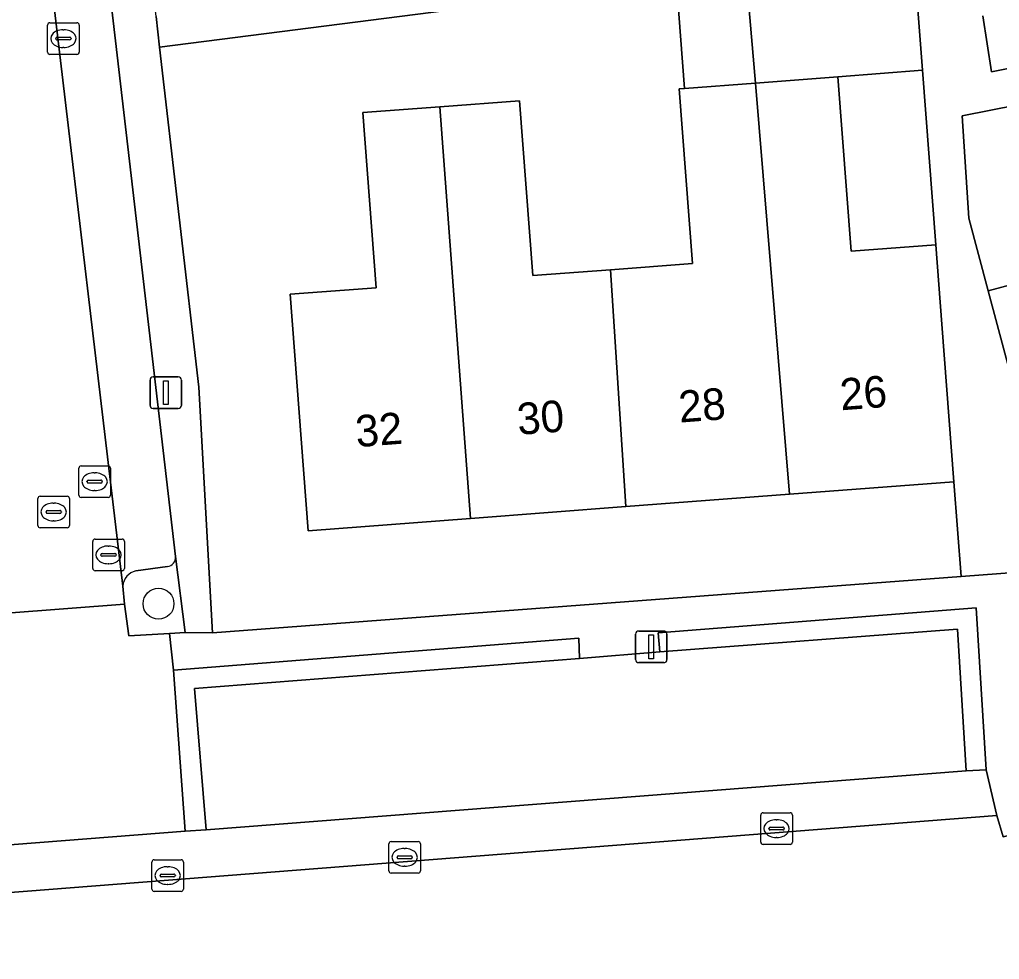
# Model space of a CAD drawing. Extents: x 162250 to 162661, y 380743 to 381606.
# Drawn here: x 162465.47 to 162496.44, y 380953.52 to 380983.23 of the extents above; entities that cross this region are included whole.
import ezdxf

# ---------------------------------------------------------------- set-up
doc = ezdxf.new("R2010")
doc.units = 0
for name, color, linetype in [('IMGEO_Boom', 7, 'Continuous'), ('IMGEO_Erf', 7, 'Continuous'), ('IMGEO_Groenvoorziening', 7, 'Continuous'), ('IMGEO_Haag', 7, 'Continuous'), ('IMGEO_Kolk', 7, 'Continuous'), ('IMGEO_Lichtmast', 7, 'Continuous'), ('IMGEO_Pand', 7, 'Continuous'), ('IMGEO_Pand_nummerreeks', 7, 'Continuous'), ('IMGEO_Parkeervlak_open', 7, 'Continuous'), ('IMGEO_Rijbaan_lokaal_open', 7, 'Continuous'), ('IMGEO_Rioolput', 7, 'Continuous'), ('IMGEO_Voetpad_open', 7, 'Continuous')]:
    doc.layers.add(name, color=color, linetype=linetype)

msp = doc.modelspace()

# ---------------------------------------------------------------- linework, layer by layer
at = {"layer": 'IMGEO_Boom'}
msp.add_circle((162469.861, 380964.762), 0.489, dxfattribs=at)
at = {"layer": 'IMGEO_Erf'}
for points in [[(162486.322, 380981.042), (162486.481, 380981.054), (162486.238, 380984.254), (162488.449, 380984.535), (162493.737, 380985.206), (162493.721, 380985.411), (162469.897, 380982.357), (162471.135, 380971.612), (162471.572, 380963.846), (162495.227, 380965.622), (162494.999, 380968.619), (162489.799, 380968.224), (162484.636, 380967.831), (162479.725, 380967.457), (162474.59, 380967.067), (162474.021, 380974.546), (162476.744, 380974.753), (162476.323, 380980.291), (162478.756, 380980.476), (162481.27, 380980.667), (162481.691, 380975.136), (162484.148, 380975.323), (162486.742, 380975.52)], [(162494.009, 380981.627), (162491.33, 380981.423), (162491.75, 380975.909), (162494.429, 380976.113)]]:
    msp.add_lwpolyline(points, close=True, dxfattribs=at)
for points in [[(162514.514, 380984.008), (162495.265, 380980.189), (162495.468, 380976.95), (162496.082, 380974.653), (162498.633, 380975.335)], [(162495.915, 380983.354), (162496.184, 380981.582), (162509.432, 380984.21)]]:
    msp.add_lwpolyline(points, dxfattribs=at)
at = {"layer": 'IMGEO_Groenvoorziening'}
for points in [[(162468.735, 380965.321), (162468.787, 380964.749), (162468.925, 380963.744), (162470.212, 380963.82), (162470.699, 380963.849), (162470.398, 380966.255)], [(162470.141, 380965.934), (162469.147, 380965.797)]]:
    msp.add_lwpolyline(points, dxfattribs=at)
for points in [[(162496.019, 380959.507), (162495.7, 380964.636), (162485.657, 380963.842), (162485.706, 380963.237), (162495.115, 380963.958), (162495.387, 380959.475)], [(162471.001, 380962.077), (162483.168, 380963.025), (162483.148, 380963.671), (162470.338, 380962.659), (162470.708, 380957.569), (162471.37, 380957.614)]]:
    msp.add_lwpolyline(points, close=True, dxfattribs=at)
for centre, radius, start, end in [((162470.106, 380966.226), 0.294, 276.9, 5.7368), ((162469.25, 380965.291), 0.516, 101.555, 176.6896)]:
    msp.add_arc(centre, radius, start, end, dxfattribs=at)
at = {"layer": 'IMGEO_Haag'}
for points in [[(162496.019, 380959.507), (162495.7, 380964.636), (162485.657, 380963.842), (162485.706, 380963.237), (162495.115, 380963.958), (162495.387, 380959.475)], [(162471.001, 380962.077), (162483.168, 380963.025), (162483.148, 380963.671), (162470.338, 380962.659), (162470.708, 380957.569), (162471.37, 380957.614)]]:
    msp.add_lwpolyline(points, close=True, dxfattribs=at)
at = {"layer": 'IMGEO_Kolk'}
for p, q in [((162466.354, 380982.204), (162466.354, 380983.056)), ((162466.429, 380983.13), (162467.281, 380983.13)), ((162467.355, 380983.056), (162467.355, 380982.204)), ((162466.842, 380982.91), (162466.867, 380982.91)), ((162466.613, 380982.624), (162466.613, 380982.636)), ((162467.051, 380982.587), (162466.653, 380982.587)), ((162466.656, 380982.673), (162467.054, 380982.673)), ((162467.097, 380982.636), (162467.097, 380982.624)), ((162467.281, 380982.13), (162466.429, 380982.13)), ((162466.865, 380982.35), (162466.84, 380982.35)), ((162467.417, 380969.121), (162468.269, 380969.121)), ((162467.342, 380968.195), (162467.342, 380969.047)), ((162467.83, 380968.901), (162467.855, 380968.901)), ((162468.343, 380969.047), (162468.343, 380968.195)), ((162467.601, 380968.615), (162467.601, 380968.627)), ((162468.039, 380968.578), (162467.641, 380968.578)), ((162467.644, 380968.664), (162468.042, 380968.664)), ((162468.085, 380968.627), (162468.085, 380968.615)), ((162467.853, 380968.341), (162467.828, 380968.341)), ((162468.269, 380968.121), (162467.417, 380968.121)), ((162488.894, 380957.225), (162488.894, 380958.077)), ((162488.969, 380958.151), (162489.821, 380958.151)), ((162489.895, 380958.077), (162489.895, 380957.225)), ((162489.153, 380957.645), (162489.153, 380957.657)), ((162489.196, 380957.694), (162489.594, 380957.694)), ((162489.382, 380957.931), (162489.407, 380957.931)), ((162489.637, 380957.657), (162489.637, 380957.645)), ((162489.591, 380957.608), (162489.193, 380957.608)), ((162489.405, 380957.371), (162489.38, 380957.371)), ((162477.14, 380956.317), (162477.14, 380957.169)), ((162477.215, 380957.243), (162478.067, 380957.243)), ((162477.628, 380957.023), (162477.653, 380957.023)), ((162478.141, 380957.169), (162478.141, 380956.317)), ((162489.821, 380957.151), (162488.969, 380957.151)), ((162477.399, 380956.737), (162477.399, 380956.749)), ((162477.442, 380956.786), (162477.84, 380956.786)), ((162477.883, 380956.749), (162477.883, 380956.737)), ((162469.65, 380955.741), (162469.65, 380956.593)), ((162469.725, 380956.667), (162470.577, 380956.667)), ((162470.138, 380956.447), (162470.163, 380956.447)), ((162470.651, 380956.593), (162470.651, 380955.741)), ((162477.837, 380956.7), (162477.439, 380956.7)), ((162477.651, 380956.463), (162477.626, 380956.463)), ((162469.909, 380956.161), (162469.909, 380956.173)), ((162470.347, 380956.124), (162469.949, 380956.124)), ((162469.952, 380956.21), (162470.35, 380956.21)), ((162470.393, 380956.173), (162470.393, 380956.161)), ((162478.067, 380956.243), (162477.215, 380956.243)), ((162470.161, 380955.887), (162470.136, 380955.887)), ((162470.577, 380955.667), (162469.725, 380955.667))]:
    msp.add_line(p, q, dxfattribs=at)
for points in [[(162466.354, 380982.204), (162466.354, 380983.056)], [(162466.429, 380983.13), (162467.281, 380983.13)], [(162467.355, 380983.056), (162467.355, 380982.204)], [(162467.281, 380982.13), (162466.429, 380982.13)], [(162467.417, 380969.121), (162468.269, 380969.121)], [(162467.342, 380968.195), (162467.342, 380969.047)], [(162468.343, 380969.047), (162468.343, 380968.195)], [(162468.269, 380968.121), (162467.417, 380968.121)], [(162488.894, 380957.225), (162488.894, 380958.077)], [(162488.969, 380958.151), (162489.821, 380958.151)], [(162489.895, 380958.077), (162489.895, 380957.225)], [(162477.14, 380956.317), (162477.14, 380957.169)], [(162477.215, 380957.243), (162478.067, 380957.243)], [(162478.141, 380957.169), (162478.141, 380956.317)], [(162489.821, 380957.151), (162488.969, 380957.151)], [(162469.65, 380955.741), (162469.65, 380956.593)], [(162469.725, 380956.667), (162470.577, 380956.667)], [(162470.651, 380956.593), (162470.651, 380955.741)], [(162478.067, 380956.243), (162477.215, 380956.243)], [(162470.577, 380955.667), (162469.725, 380955.667)]]:
    msp.add_lwpolyline(points, dxfattribs=at)
for centre, radius, start, end in [((162466.431, 380983.054), 0.0765, 91.552, 178.448), ((162466.431, 380983.054), 0.0765, 91.552, 178.448), ((162467.279, 380983.054), 0.0765, 1.552, 88.448), ((162467.279, 380983.054), 0.0765, 1.552, 88.448), ((162466.653, 380982.633), 0.0403, 85.8775, 175.7526), ((162466.65, 380982.623), 0.0366, 178.938, 274.7102), ((162467.054, 380982.63), 0.043, 264.8664, 352.4533), ((162467.058, 380982.635), 0.0386, 1.7309, 96.639), ((162466.431, 380982.206), 0.0765, 181.552, 268.448), ((162466.431, 380982.206), 0.0765, 181.552, 268.448), ((162467.279, 380982.206), 0.0765, 271.552, 358.448), ((162467.279, 380982.206), 0.0765, 271.552, 358.448), ((162467.419, 380969.045), 0.0765, 91.552, 178.448), ((162467.419, 380969.045), 0.0765, 91.552, 178.448), ((162468.267, 380969.045), 0.0765, 1.552, 88.448), ((162468.267, 380969.045), 0.0765, 1.552, 88.448), ((162467.641, 380968.624), 0.0403, 85.8775, 175.7526), ((162467.638, 380968.614), 0.0366, 178.938, 274.7102), ((162468.042, 380968.621), 0.043, 264.8664, 352.4533), ((162468.046, 380968.626), 0.0386, 1.7309, 96.639), ((162467.419, 380968.197), 0.0765, 181.552, 268.448), ((162467.419, 380968.197), 0.0765, 181.552, 268.448), ((162468.267, 380968.197), 0.0765, 271.552, 358.448), ((162468.267, 380968.197), 0.0765, 271.552, 358.448), ((162488.971, 380958.075), 0.0765, 91.552, 178.448), ((162488.971, 380958.075), 0.0765, 91.552, 178.448), ((162489.819, 380958.075), 0.0765, 1.552, 88.448), ((162489.819, 380958.075), 0.0765, 1.552, 88.448), ((162489.193, 380957.654), 0.0403, 85.8775, 175.7526), ((162489.19, 380957.644), 0.0366, 178.938, 274.7102), ((162489.594, 380957.651), 0.043, 264.8664, 352.4533), ((162489.598, 380957.656), 0.0386, 1.7309, 96.639), ((162477.217, 380957.167), 0.0765, 91.552, 178.448), ((162477.217, 380957.167), 0.0765, 91.552, 178.448), ((162478.065, 380957.167), 0.0765, 1.552, 88.448), ((162478.065, 380957.167), 0.0765, 1.552, 88.448), ((162488.971, 380957.227), 0.0765, 181.552, 268.448), ((162488.971, 380957.227), 0.0765, 181.552, 268.448), ((162489.819, 380957.227), 0.0765, 271.552, 358.448), ((162489.819, 380957.227), 0.0765, 271.552, 358.448), ((162477.439, 380956.746), 0.0403, 85.8775, 175.7526), ((162477.436, 380956.736), 0.0366, 178.938, 274.7102), ((162477.84, 380956.743), 0.043, 264.8664, 352.4533), ((162477.844, 380956.748), 0.0386, 1.7309, 96.639), ((162469.727, 380956.591), 0.0765, 91.552, 178.448), ((162469.727, 380956.591), 0.0765, 91.552, 178.448), ((162470.575, 380956.591), 0.0765, 1.552, 88.448), ((162470.575, 380956.591), 0.0765, 1.552, 88.448), ((162469.949, 380956.17), 0.0403, 85.8775, 175.7526), ((162469.946, 380956.16), 0.0366, 178.938, 274.7102), ((162470.35, 380956.167), 0.043, 264.8664, 352.4533), ((162470.354, 380956.172), 0.0386, 1.7309, 96.639), ((162477.217, 380956.319), 0.0765, 181.552, 268.448), ((162477.217, 380956.319), 0.0765, 181.552, 268.448), ((162478.065, 380956.319), 0.0765, 271.552, 358.448), ((162478.065, 380956.319), 0.0765, 271.552, 358.448), ((162469.727, 380955.743), 0.0765, 181.552, 268.448), ((162469.727, 380955.743), 0.0765, 181.552, 268.448), ((162470.575, 380955.743), 0.0765, 271.552, 358.448), ((162470.575, 380955.743), 0.0765, 271.552, 358.448)]:
    msp.add_arc(centre, radius, start, end, dxfattribs=at)
for centre, major_axis, ratio, start_param, end_param in [((162466.841, 380982.63), (-0.387, 0.002), 0.722429, 4.712389, 7.853982), ((162466.866, 380982.63), (-0.39, 0.002), 0.717154, 1.570796, 4.712389), ((162467.829, 380968.621), (-0.387, 0.002), 0.722429, 4.712389, 7.853982), ((162467.854, 380968.621), (-0.39, 0.002), 0.717154, 1.570796, 4.712389), ((162489.381, 380957.651), (-0.387, 0.002), 0.722429, 4.712389, 7.853982), ((162489.406, 380957.651), (-0.39, 0.002), 0.717154, 1.570796, 4.712389), ((162477.627, 380956.743), (-0.387, 0.002), 0.722429, 4.712389, 7.853982), ((162477.652, 380956.743), (-0.39, 0.002), 0.717154, 1.570796, 4.712389), ((162470.137, 380956.167), (-0.387, 0.002), 0.722429, 4.712389, 7.853982), ((162470.162, 380956.167), (-0.39, 0.002), 0.717154, 1.570796, 4.712389)]:
    msp.add_ellipse(centre, major_axis=major_axis, ratio=ratio, start_param=start_param, end_param=end_param, dxfattribs=at)
at = {"layer": 'IMGEO_Lichtmast'}
for p, q in [((162469.694, 380971.933), (162470.484, 380971.933)), ((162470.484, 380971.933), (162469.694, 380971.933)), ((162469.594, 380971.033), (162469.594, 380971.833)), ((162469.594, 380971.833), (162469.594, 380971.033)), ((162470.584, 380971.833), (162470.584, 380971.033)), ((162470.584, 380971.033), (162470.584, 380971.833)), ((162470.484, 380970.933), (162469.694, 380970.933)), ((162469.694, 380970.933), (162470.484, 380970.933)), ((162485.04, 380963.899), (162485.83, 380963.899)), ((162485.83, 380963.899), (162485.04, 380963.899)), ((162484.94, 380962.999), (162484.94, 380963.799)), ((162484.94, 380963.799), (162484.94, 380962.999)), ((162485.93, 380963.799), (162485.93, 380962.999)), ((162485.93, 380962.999), (162485.93, 380963.799)), ((162485.83, 380962.899), (162485.04, 380962.899)), ((162485.04, 380962.899), (162485.83, 380962.899))]:
    msp.add_line(p, q, dxfattribs=at)
for points in [[(162470.014, 380971.808), (162470.164, 380971.808), (162470.164, 380971.058), (162470.014, 380971.058), (162470.014, 380971.808)], [(162485.36, 380963.774), (162485.51, 380963.774), (162485.51, 380963.024), (162485.36, 380963.024), (162485.36, 380963.774)]]:
    msp.add_lwpolyline(points, dxfattribs=at)
for centre, start, end in [((162469.694, 380971.833), 90, 180), ((162469.694, 380971.833), 90, 180), ((162470.484, 380971.833), 0, 90), ((162470.484, 380971.833), 360, 90), ((162469.694, 380971.033), 180, 270), ((162469.694, 380971.033), 180, 270), ((162470.484, 380971.033), 270, 0), ((162470.484, 380971.033), 270, 0), ((162485.04, 380963.799), 90, 180), ((162485.04, 380963.799), 90, 180), ((162485.83, 380963.799), 0, 90), ((162485.83, 380963.799), 360, 90), ((162485.04, 380962.999), 180, 270), ((162485.04, 380962.999), 180, 270), ((162485.83, 380962.999), 270, 0), ((162485.83, 380962.999), 270, 0)]:
    msp.add_arc(centre, 0.1, start, end, dxfattribs=at)
at = {"layer": 'IMGEO_Pand'}
for points in [[(162493.737, 380985.206), (162488.449, 380984.535), (162488.728, 380981.225), (162491.33, 380981.423), (162494.009, 380981.627)], [(162488.449, 380984.535), (162486.238, 380984.254), (162486.481, 380981.054), (162488.728, 380981.225)], [(162488.728, 380981.225), (162486.481, 380981.054), (162486.322, 380981.042), (162486.742, 380975.52), (162484.148, 380975.323), (162484.636, 380967.831), (162489.799, 380968.224)], [(162488.728, 380981.225), (162489.799, 380968.224), (162494.999, 380968.619), (162494.62, 380973.605), (162494.429, 380976.113), (162491.75, 380975.909), (162491.33, 380981.423)], [(162478.756, 380980.476), (162479.725, 380967.457), (162484.636, 380967.831), (162484.148, 380975.323), (162481.691, 380975.136), (162481.27, 380980.667)], [(162478.756, 380980.476), (162476.323, 380980.291), (162476.744, 380974.753), (162474.021, 380974.546), (162474.59, 380967.067), (162479.725, 380967.457)], [(162500.261, 380978.292), (162500, 380978.222), (162498.004, 380977.689), (162498.633, 380975.335), (162496.082, 380974.653), (162498.432, 380965.863), (162498.83, 380964.374), (162500, 380964.687), (162503.731, 380965.684)]]:
    msp.add_lwpolyline(points, close=True, dxfattribs=at)
at = {"layer": 'IMGEO_Parkeervlak_open'}
for points in [[(162466.443, 380984.612), (162468.735, 380965.321)], [(162470.398, 380966.255), (162468.323, 380984.109)], [(162469.147, 380965.797), (162470.141, 380965.934)]]:
    msp.add_lwpolyline(points, dxfattribs=at)
msp.add_lwpolyline([(162485.706, 380963.237), (162483.168, 380963.025), (162471.001, 380962.077), (162471.37, 380957.614), (162495.387, 380959.475), (162495.115, 380963.958)], close=True, dxfattribs=at)
for centre, radius, start, end in [((162470.106, 380966.226), 0.294, 276.9, 5.7368), ((162469.25, 380965.291), 0.516, 101.555, 176.6896)]:
    msp.add_arc(centre, radius, start, end, dxfattribs=at)
at = {"layer": 'IMGEO_Rijbaan_lokaal_open'}
for points in [[(162460.5, 381035.516), (162460.418, 381036.093), (162456.733, 381035.695), (162458.261, 381022.719), (162458.412, 381021.524), (162461.237, 380997.285), (162461.392, 380996.087), (162464.213, 380971.852), (162464.376, 380970.663), (162465.07, 380964.466), (162468.787, 380964.749), (162468.735, 380965.321), (162466.443, 380984.612), (162466.298, 380985.818), (162463.47, 381010.085), (162463.312, 381011.262)], [(162470.338, 380962.659), (162470.212, 380963.82), (162468.925, 380963.744), (162468.787, 380964.749), (162465.07, 380964.466), (162465.132, 380963.42), (162463.931, 380963.326), (162463.987, 380962.195), (162464.477, 380957.086), (162470.708, 380957.569)], [(162496.357, 380958.063), (162496.019, 380959.507), (162495.387, 380959.475), (162471.37, 380957.614), (162470.708, 380957.569), (162464.477, 380957.086), (162463.767, 380957.044), (162439.86, 380955.003), (162439.221, 380954.971), (162439.259, 380953.604)], [(162438.734, 380949.347), (162439.723, 380949.226), (162439.832, 380947.218), (162439.893, 380946.084), (162442.323, 380945.804), (162494.027, 380950.024), (162498.35, 380950.984), (162497.589, 380953.806), (162498.576, 380954.116), (162497.59, 380957.646), (162496.558, 380957.39), (162496.357, 380958.063), (162439.259, 380953.604), (162439.321, 380953.087), (162438.396, 380953.171), (162438.711, 380949.35)]]:
    msp.add_lwpolyline(points, close=True, dxfattribs=at)
at = {"layer": 'IMGEO_Rioolput'}
for p, q in [((162466.122, 380968.162), (162466.974, 380968.162)), ((162466.047, 380967.236), (162466.047, 380968.088)), ((162466.535, 380967.942), (162466.56, 380967.942)), ((162467.048, 380968.088), (162467.048, 380967.236)), ((162466.306, 380967.656), (162466.306, 380967.668)), ((162466.744, 380967.619), (162466.346, 380967.619)), ((162466.349, 380967.705), (162466.747, 380967.705)), ((162466.79, 380967.668), (162466.79, 380967.656)), ((162466.558, 380967.382), (162466.533, 380967.382)), ((162466.974, 380967.162), (162466.122, 380967.162)), ((162467.781, 380965.88), (162467.781, 380966.732)), ((162467.856, 380966.806), (162468.708, 380966.806)), ((162468.782, 380966.732), (162468.782, 380965.88)), ((162468.04, 380966.3), (162468.04, 380966.312)), ((162468.083, 380966.349), (162468.481, 380966.349)), ((162468.269, 380966.586), (162468.294, 380966.586)), ((162468.524, 380966.312), (162468.524, 380966.3)), ((162468.478, 380966.263), (162468.08, 380966.263)), ((162468.292, 380966.026), (162468.267, 380966.026)), ((162468.708, 380965.806), (162467.856, 380965.806))]:
    msp.add_line(p, q, dxfattribs=at)
for points in [[(162466.122, 380968.162), (162466.974, 380968.162)], [(162466.047, 380967.236), (162466.047, 380968.088)], [(162467.048, 380968.088), (162467.048, 380967.236)], [(162466.974, 380967.162), (162466.122, 380967.162)], [(162467.781, 380965.88), (162467.781, 380966.732)], [(162467.856, 380966.806), (162468.708, 380966.806)], [(162468.782, 380966.732), (162468.782, 380965.88)], [(162468.708, 380965.806), (162467.856, 380965.806)]]:
    msp.add_lwpolyline(points, dxfattribs=at)
for centre, radius, start, end in [((162466.124, 380968.086), 0.0765, 91.552, 178.448), ((162466.124, 380968.086), 0.0765, 91.552, 178.448), ((162466.972, 380968.086), 0.0765, 1.552, 88.448), ((162466.972, 380968.086), 0.0765, 1.552, 88.448), ((162466.346, 380967.665), 0.0403, 85.8775, 175.7526), ((162466.343, 380967.655), 0.0366, 178.938, 274.7102), ((162466.747, 380967.662), 0.043, 264.8664, 352.4533), ((162466.751, 380967.667), 0.0386, 1.7309, 96.639), ((162466.124, 380967.238), 0.0765, 181.552, 268.448), ((162466.124, 380967.238), 0.0765, 181.552, 268.448), ((162466.972, 380967.238), 0.0765, 271.552, 358.448), ((162466.972, 380967.238), 0.0765, 271.552, 358.448), ((162467.858, 380966.73), 0.0765, 91.552, 178.448), ((162467.858, 380966.73), 0.0765, 91.552, 178.448), ((162468.706, 380966.73), 0.0765, 1.552, 88.448), ((162468.706, 380966.73), 0.0765, 1.552, 88.448), ((162468.08, 380966.309), 0.0403, 85.8775, 175.7526), ((162468.485, 380966.311), 0.0386, 1.7309, 96.639), ((162468.077, 380966.299), 0.0366, 178.938, 274.7102), ((162468.481, 380966.306), 0.043, 264.8664, 352.4533), ((162467.858, 380965.882), 0.0765, 181.552, 268.448), ((162467.858, 380965.882), 0.0765, 181.552, 268.448), ((162468.706, 380965.882), 0.0765, 271.552, 358.448), ((162468.706, 380965.882), 0.0765, 271.552, 358.448)]:
    msp.add_arc(centre, radius, start, end, dxfattribs=at)
for centre, major_axis, ratio, start_param, end_param in [((162466.534, 380967.662), (-0.387, 0.002), 0.722429, 4.712389, 7.853982), ((162466.559, 380967.662), (-0.39, 0.002), 0.717154, 1.570796, 4.712389), ((162468.268, 380966.306), (-0.387, 0.002), 0.722429, 4.712389, 7.853982), ((162468.293, 380966.306), (-0.39, 0.002), 0.717154, 1.570796, 4.712389)]:
    msp.add_ellipse(centre, major_axis=major_axis, ratio=ratio, start_param=start_param, end_param=end_param, dxfattribs=at)
at = {"layer": 'IMGEO_Voetpad_open'}
for points in [[(162462.351, 381035.014), (162465.026, 381012.162), (162465.322, 381009.581), (162467.991, 380986.747), (162468.323, 380984.109), (162470.398, 380966.255), (162470.699, 380963.849), (162471.572, 380963.846), (162471.135, 380971.612), (162469.897, 380982.357), (162469.785, 380983.331), (162467.864, 381000), (162462.62, 381045.107), (162455.21, 381107.834)], [(162469.785, 380983.331), (162469.897, 380982.357), (162493.721, 380985.411)], [(162493.737, 380985.206), (162494.009, 380981.627), (162494.429, 380976.113), (162494.62, 380973.605), (162494.999, 380968.619), (162495.227, 380965.622), (162498.432, 380965.863), (162496.082, 380974.653), (162495.468, 380976.95), (162495.265, 380980.189), (162514.514, 380984.008)], [(162509.432, 380984.21), (162496.184, 380981.582), (162495.915, 380983.354)], [(162498.385, 380964.311), (162498.83, 380964.374), (162498.432, 380965.863), (162495.227, 380965.622), (162471.572, 380963.846), (162470.699, 380963.849), (162470.212, 380963.82), (162470.338, 380962.659), (162483.148, 380963.671), (162483.168, 380963.025), (162485.706, 380963.237), (162485.657, 380963.842), (162495.7, 380964.636), (162496.019, 380959.507), (162496.357, 380958.063), (162496.558, 380957.39), (162497.59, 380957.646), (162498.589, 380957.94)]]:
    msp.add_lwpolyline(points, dxfattribs=at)

# ---------------------------------------------------------------- texts
at = {"layer": 'IMGEO_Pand_nummerreeks'}
for s, p in [('26', (162491.433, 380970.875)), ('28', (162486.334, 380970.487)), ('30', (162481.231, 380970.099)), ('32', (162476.123, 380969.711))]:
    msp.add_text(s, height=1, rotation=4.3487, dxfattribs=at).set_placement(p)

doc.saveas('drawing.dxf')
